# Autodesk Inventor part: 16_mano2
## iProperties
Created: 2002-11
Part Number: 16_mano2
Material: Par défaut
Document SubType Name: Modélisation
Designer: FIEVET
Control State: 0
Master: False
Checked Out: False
Shininess: 20.0
Length Units: 11269
Angle Units: 11279
Time Units: 11290
Mass Units: 11283
Length Display Precision: 3
Angle Display Precision: 2
Compacted: True
Density: 0.0
Volumn: 0.0
Area: 0.0
PropertySet Name: Model Information
Author: FIEVET
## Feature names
1. Extrusion1
